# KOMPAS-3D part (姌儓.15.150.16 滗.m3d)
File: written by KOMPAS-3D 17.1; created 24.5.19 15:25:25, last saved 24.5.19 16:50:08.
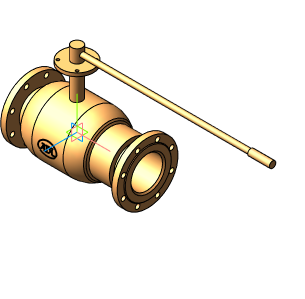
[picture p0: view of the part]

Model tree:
1. Операция без истории:2  (labels: Сталь 20  ГОСТ 1050-2013)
